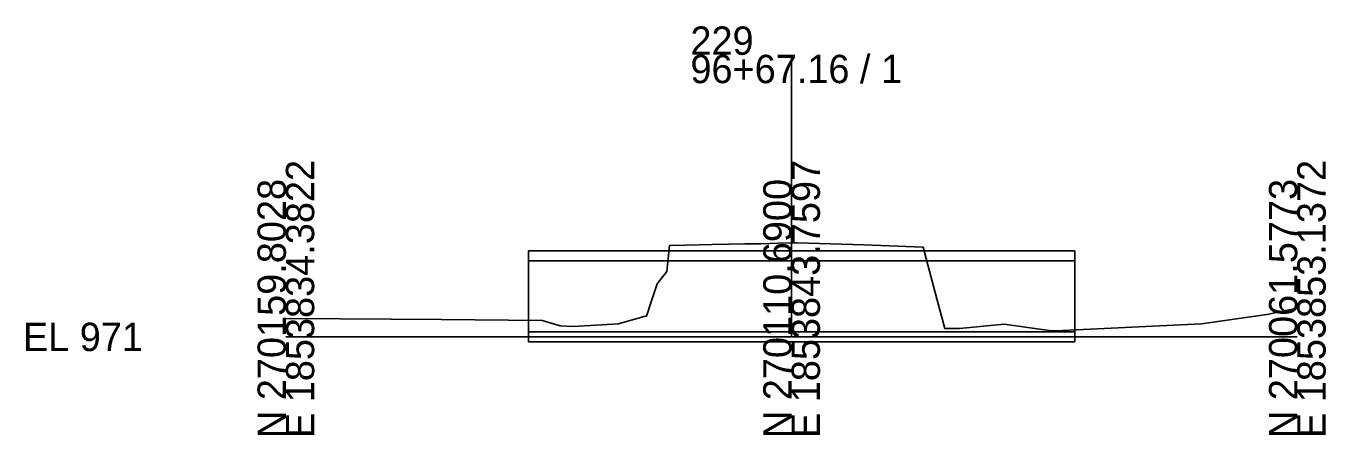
# Model space of a CAD drawing. Extents: x -26 to 103, y 1990 to 2031.
import ezdxf

# ---------------------------------------------------------------- set-up
doc = ezdxf.new("R2010")
doc.units = 0
for name, color, linetype in [('DR_P_Culvert', 7, 'Continuous'), ('GK_Cells', 7, 'Continuous'), ('XS_X_Ground_Line', 7, 'Continuous')]:
    doc.layers.add(name, color=color, linetype=linetype)

msp = doc.modelspace()

# ---------------------------------------------------------------- linework, layer by layer
at = {"layer": 'DR_P_Culvert'}
for p, q in [((24, 1999.5), (24, 2008.5)), ((24, 2008.5), (78, 2008.5)), ((78, 1999.5), (78, 2008.5)), ((24, 2007.5), (78, 2007.5)), ((24, 2000.5), (78, 2000.5)), ((24, 1999.5), (78, 1999.5))]:
    msp.add_line(p, q, dxfattribs=at)
at = {"layer": 'GK_Cells'}
for p, q in [((50, 2000), (50, 2027.87)), ((0, 2000), (50, 2000)), ((50, 2000), (100, 2000))]:
    msp.add_line(p, q, dxfattribs=at)
at = {"layer": 'XS_X_Ground_Line'}
msp.add_lwpolyline([(0, 2001.79), (0.41, 2001.8), (15.4, 2001.72), (25.35, 2001.61), (27.12, 2001.09), (28.41, 2001.02), (32.88, 2001.28), (35.51, 2002.06), (35.65, 2002.06), (36.08, 2003.38), (36.71, 2005.24), (37.66, 2006.46), (37.92, 2009.03), (39.49, 2009.05), (42.16, 2009.13), (45.37, 2009.18), (46.23, 2009.2), (46.94, 2009.2), (48.67, 2009.25), (50, 2009.28), (50.54, 2009.29), (53.85, 2009.18), (57.15, 2009.08), (63.01, 2008.88), (64.36, 2003.75), (65.15, 2000.83), (66.59, 2000.82), (71.01, 2001.27), (75.7, 2000.59), (76.11, 2000.61), (90.53, 2001.28), (97, 2002.21), (100, 2002.83)], dxfattribs=at)

# ---------------------------------------------------------------- texts
at = {"layer": 'GK_Cells'}
for s, p in [('229', (40, 2027.87)), ('96+67.16 / 1', (40, 2025.07)), ('EL 971', (-26, 1998.6))]:
    msp.add_text(s, height=2.8, dxfattribs=at).set_placement(p)
for s, p in [('E 1853834.3822', (2.8, 1990)), ('E 1853843.7597', (52.8, 1990)), ('E 1853853.1372', (102.8, 1990)), ('N 270159.8028', (0, 1990)), ('N 270110.6900', (50, 1990)), ('N 270061.5773', (100, 1990))]:
    msp.add_text(s, height=2.8, rotation=90, dxfattribs=at).set_placement(p)

doc.saveas('drawing.dxf')
